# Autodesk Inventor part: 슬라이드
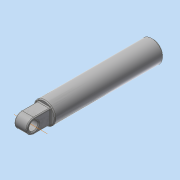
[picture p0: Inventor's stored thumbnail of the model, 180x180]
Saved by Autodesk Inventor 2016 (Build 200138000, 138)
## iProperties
Created: 2016-02
Part Number: 슬라이드
Material: 강철, 연강
Document SubType Name: Modeling
Designer: test
Density: 1 g/cm^3
Appearance: 강철
Author: test
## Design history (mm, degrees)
sketch "스케치2"
  geometry: C1 r 6 at (0, 0); 1 further point
  constraints: 1 centre point, 1 coincident
  dimensions: "d0" = 12 diameter of C1
extrude "돌출1" new body sketch "스케치2" distance "d1" = 60; taper "d2" = 0 deg
hole "구멍1" diameter "d5" = 5.917; stored, may be unused: countersink angle "d9" = 90 deg, drill point angle "d11" = 118 deg; dims "d3" = 10, "d4" = 10, "d6" = 10, "d7" = 4, "d8" = 2, "d10" = 12
chamfer "모따기1" distance "d12" = 1; stored, may be unused: second distance "d13" = 2, angle "d14" = 45 deg
sketch "스케치3"
  geometry: L1 (0, 6)-(0, -6) reference; L2 (0, 4)-(-9, 4); L3 (-9, -4)-(0, -4); L4 (0, -4)-(0, 4); C1 r 2.5 at (-9, 0); A1 r 4 centre (-9, 0) between (-9, 4) and (-9, -4); 2 further points
  constraints: 6 end point, 2 centre point, 2 point on circle, 2 tangent, 1 coincident, 1 horizontal, 1 horizontal alignment, 1 midpoint, 1 parallel, 1 point on line, 1 vertical
  dimensions: "d15" = 13 dimension on A1 L1; "d16" = 8 distance between parallel lines of L3 L2; "d17" = 5 diameter of C1
extrude "돌출2" join sketch "스케치3" stored distance "d18" = 7; taper "d19" = 0 deg
chamfer "모따기2" distance "d20" = 0.5; stored, may be unused: second distance "d21" = 2, angle "d22" = 45 deg
fillet "모깎기1" dims "d23" = 0.5
fillet "모깎기2" dims "d24" = 0.5
fillet "모깎기3" dims "d25" = 0.5
node "작업축1"
node "솔리드1"
